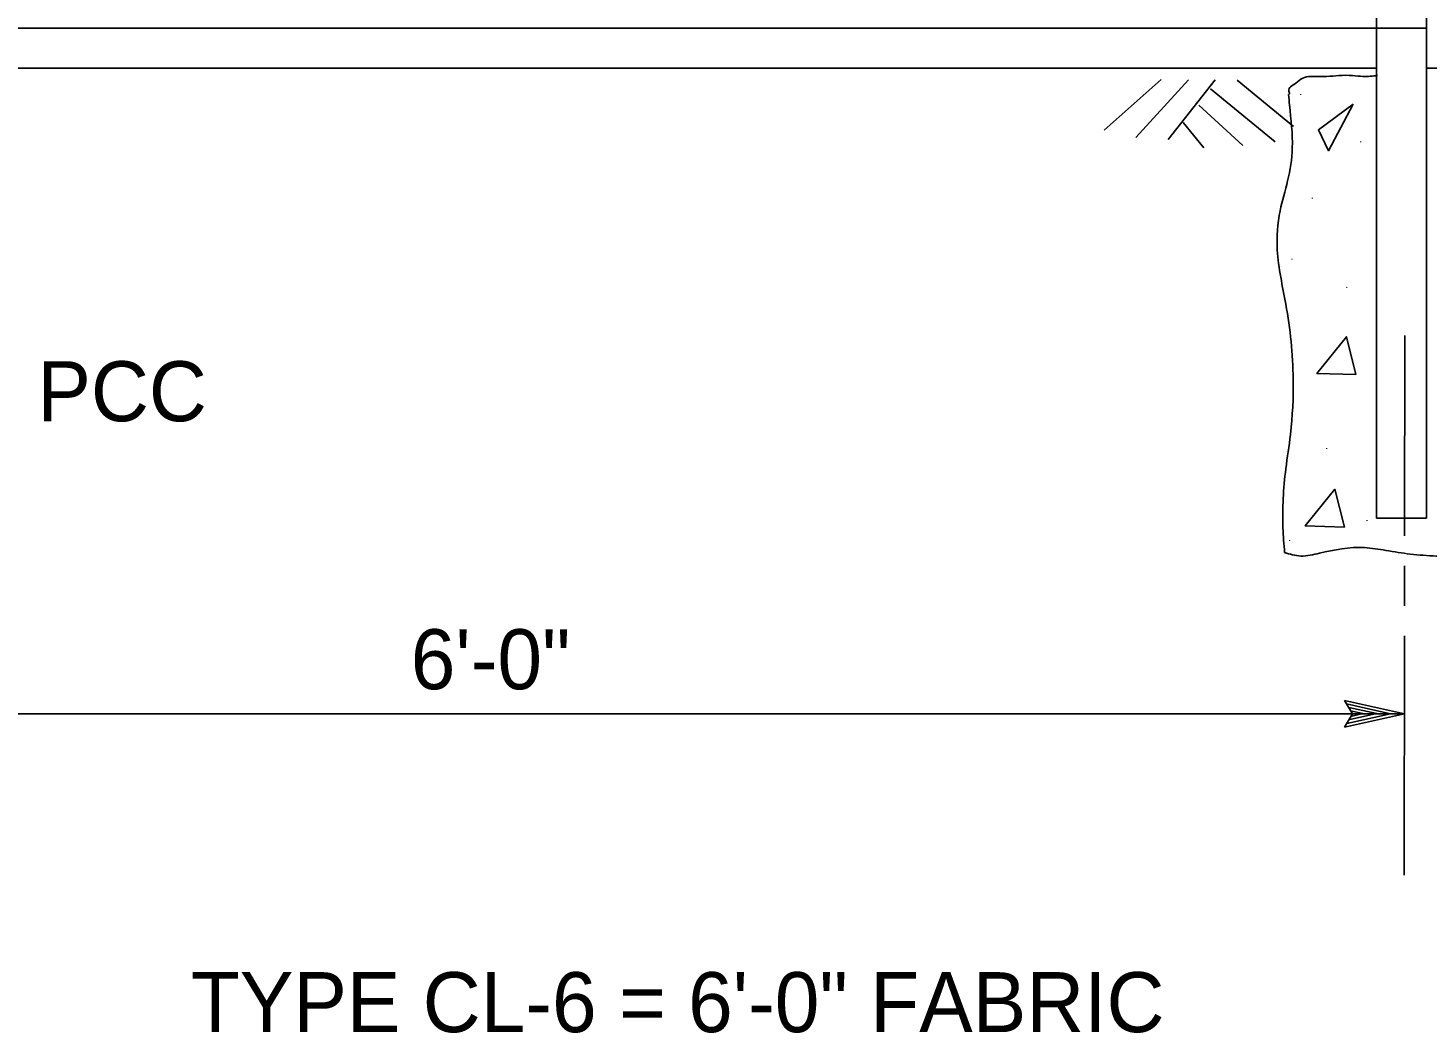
# Model space of a CAD drawing. Extents: x -123486 to -116575, y -107066 to -101122.
# Drawn here: x -118499.6 to -118359.8, y -102107 to -102006.5 of the extents above; entities that cross this region are included whole.
import ezdxf

# ---------------------------------------------------------------- set-up
doc = ezdxf.new("R2010")
doc.units = 0
for name, color, linetype in [('G-MARK', 7, 'Continuous'), ('G-TEXT', 7, 'Continuous'), ('Misc CnstDet(22)', 7, 'Continuous'), ('Nongeo Data(60)', 7, 'Continuous')]:
    doc.layers.add(name, color=color, linetype=linetype)

msp = doc.modelspace()

# ---------------------------------------------------------------- linework, layer by layer
at = {"layer": 'G-MARK'}
msp.add_line((-118538.9, -102075.04), (-118362.01, -102075.04), dxfattribs=at)
for points in [[(-118361.97, -102037.24), (-118361.99, -102057.24)], [(-118361.99, -102060.24), (-118362, -102064.24)], [(-118362, -102067.24), (-118362.03, -102091.18)]]:
    msp.add_lwpolyline(points, dxfattribs=at)
at = {"layer": 'G-TEXT'}
for p, q in [((-118367.21, -102075.04), (-118368.01, -102073.7)), ((-118368.01, -102073.7), (-118368.01, -102073.7)), ((-118368.01, -102073.7), (-118362.01, -102075.04)), ((-118362.01, -102075.04), (-118368.01, -102076.37)), ((-118368.01, -102076.37), (-118367.21, -102075.04)), ((-118367.8, -102074.05), (-118363.39, -102075.04)), ((-118363.4, -102075.04), (-118367.78, -102076.01)), ((-118364.77, -102075.03), (-118367.6, -102075.66)), ((-118367.56, -102074.41), (-118364.77, -102075.03)), ((-118367.39, -102074.76), (-118366.16, -102075.03)), ((-118366.16, -102075.03), (-118367.36, -102075.3)), ((-118362.01, -102075.04), (-118362.01, -102075.04)), ((-118368.01, -102076.37), (-118368.01, -102076.37))]:
    msp.add_line(p, q, dxfattribs=at)
at = {"layer": 'Nongeo Data(60)'}
for p, q in [((-118364.8, -102055.5), (-118364.8, -101996.14)), ((-118359.8, -102055.5), (-118359.8, -101996.14)), ((-118359.8, -102006.5), (-118535.15, -102006.5)), ((-118364.8, -102010.5), (-118536.8, -102010.5)), ((-118157.18, -102010.5), (-118359.8, -102010.5)), ((-118386.33, -102011.62), (-118392.03, -102016.7)), ((-118383.59, -102011.66), (-118388.88, -102017.42)), ((-118380.92, -102011.66), (-118385.62, -102017.64)), ((-118378.73, -102011.69), (-118373.09, -102016.33)), ((-118381.39, -102012.56), (-118374.94, -102017.86)), ((-118382.56, -102014.21), (-118378.16, -102018.22)), ((-118384.12, -102015.93), (-118382.06, -102018.46)), ((-118359.8, -102055.5), (-118364.8, -102055.5)), ((-118359.8, -102055.5), (-118364.8, -102055.5)), ((-118359.8, -102055.5), (-118364.8, -102055.5))]:
    msp.add_line(p, q, dxfattribs=at)
for points in [[(-118367.13, -102014.11), (-118369.6, -102018.76), (-118370.62, -102016.68)], [(-118366.87, -102041.12), (-118370.77, -102041.01), (-118367.82, -102037.35)], [(-118368.02, -102056.37), (-118371.93, -102056.26), (-118368.97, -102052.6)]]:
    msp.add_lwpolyline(points, close=True, dxfattribs=at)
for points in [[(-118373.6, -102013.14), (-118373.56, -102013.13), (-118373.56, -102012.79), (-118373.39, -102012.36), (-118372.87, -102012.01), (-118372.18, -102011.5), (-118371.41, -102011.33), (-118369.78, -102011.33), (-118368.57, -102011.24), (-118367.19, -102011.24), (-118366.16, -102011.33), (-118364.7, -102011.24)], [(-118373.6, -102013.14), (-118373.5, -102014.18), (-118373.22, -102018.48), (-118373.69, -102021.76), (-118374.44, -102024.75), (-118374.72, -102028.68), (-118373.87, -102034.1), (-118373.13, -102041.59), (-118373.41, -102047.11), (-118373.87, -102050.57), (-118374.16, -102056.46), (-118373.99, -102058.92)], [(-118373.99, -102058.92), (-118372.38, -102059.27), (-118370.51, -102058.99), (-118366.02, -102058.43), (-118363.86, -102058.71), (-118361.43, -102059.08), (-118358.81, -102059.27), (-118355.91, -102059.36), (-118353.2, -102059.27), (-118351.61, -102059.08), (-118350.99, -102058.92)]]:
    msp.add_spline(points, degree=3, dxfattribs=at)

# ---------------------------------------------------------------- texts
at = {"layer": 'Misc CnstDet(22)'}
msp.add_text('TYPE CL-6 = 6\'-0" FABRIC', height=6, dxfattribs=at).set_placement((-118483.35, -102106.87))
at = {"layer": 'Nongeo Data(60)'}
for p in [(-118372.43, -102012.98), (-118366.44, -102017.71), (-118371.28, -102023.34), (-118373.32, -102029.45), (-118367.83, -102032.26), (-118369.84, -102048.37), (-118365.81, -102055.56), (-118373.55, -102057.56)]:
    msp.add_text('.', height=0.8, rotation=266.9315, dxfattribs=at).set_placement(p)
for s, p in [('PCC', (-118498.69, -102045.8)), ('6\'-0"', (-118461.36, -102072.59))]:
    msp.add_text(s, height=6, dxfattribs=at).set_placement(p)

doc.saveas('drawing.dxf')
